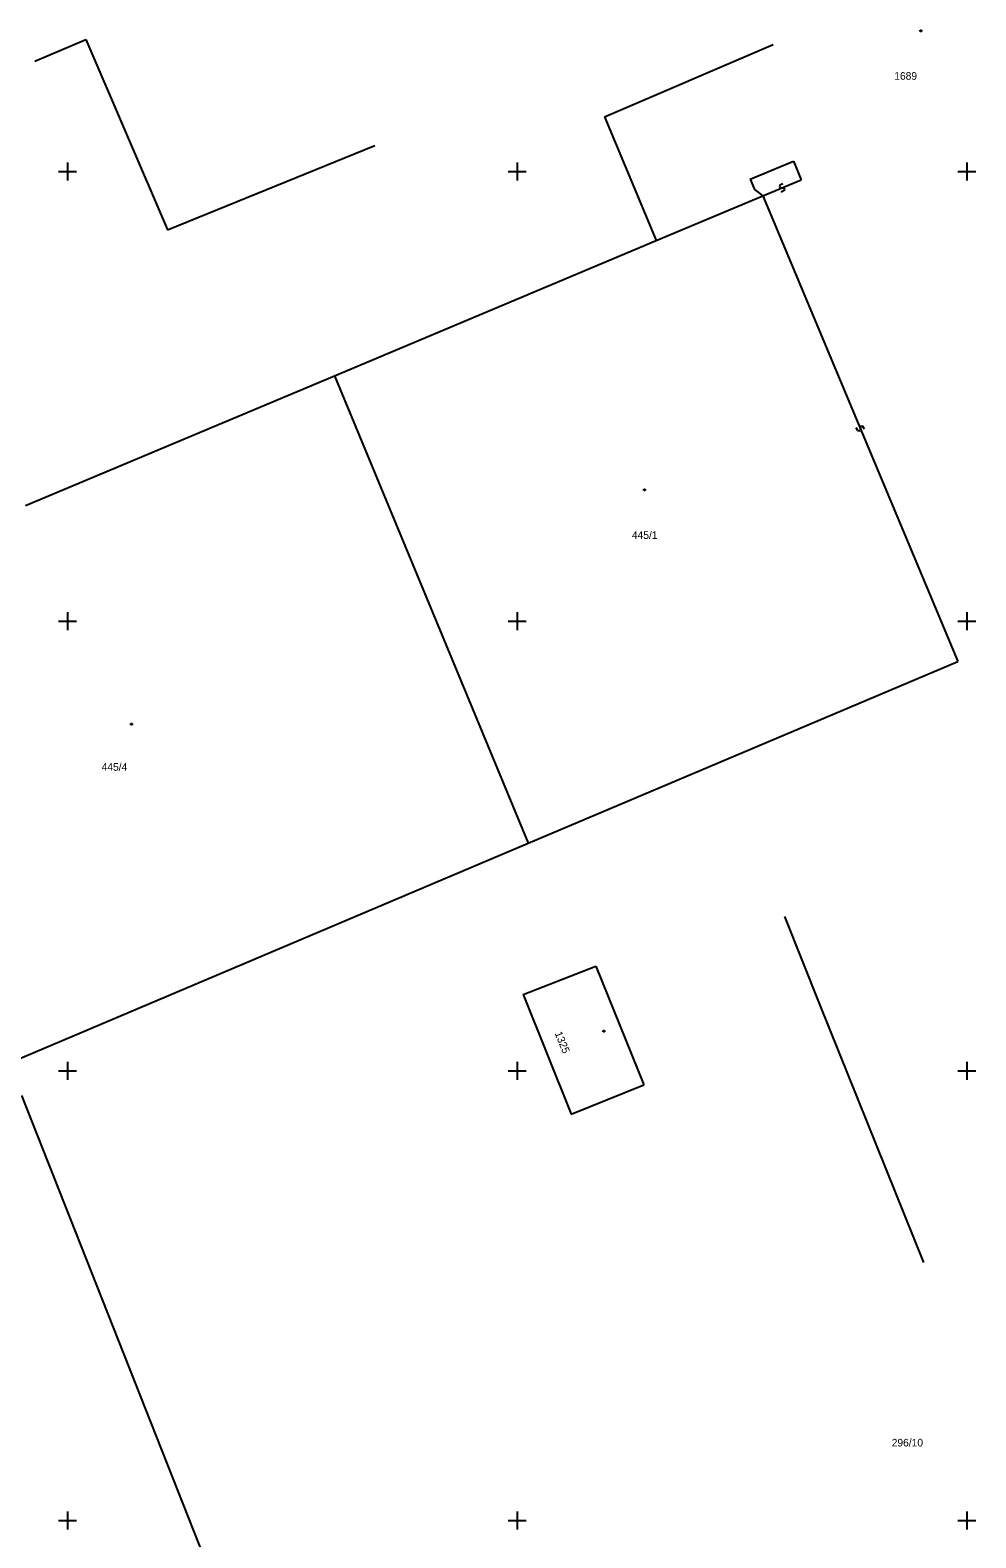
# Model space of a CAD drawing. Extents: x -492379 to -491966, y -1126153 to -1125860.
# Drawn here: x -492032.5 to -491969.4, y -1125961.2 to -1125860.6 of the extents above; entities that cross this region are included whole.
import ezdxf

# ---------------------------------------------------------------- set-up
doc = ezdxf.new("R2010")
doc.units = 0
doc.layers.add('katastrální mapa', color=7, linetype='Continuous')
doc.layers.add('síť', color=7, linetype='Continuous')

msp = doc.modelspace()

# ---------------------------------------------------------------- linework, layer by layer
at = {"layer": 'katastrální mapa'}
for p, q in [((-491973.11, -1125860.58), (-491973.02, -1125860.58)), ((-491973.11, -1125860.67), (-491973.11, -1125860.58)), ((-491973.02, -1125860.67), (-491973.11, -1125860.67)), ((-491973.02, -1125860.58), (-491973.02, -1125860.67)), ((-492032.17, -1125862.65), (-492028.77, -1125861.2)), ((-492028.77, -1125861.2), (-492023.33, -1125873.91)), ((-491994.18, -1125866.37), (-491982.91, -1125861.53)), ((-491994.18, -1125866.37), (-491990.72, -1125874.62)), ((-492023.33, -1125873.91), (-492009.49, -1125868.27)), ((-491984.45, -1125870.52), (-491981.57, -1125869.31)), ((-491981.57, -1125869.31), (-491981.05, -1125870.57)), ((-491984.45, -1125870.52), (-491984.17, -1125871.2)), ((-491983.61, -1125871.64), (-491981.05, -1125870.57)), ((-491982.47, -1125870.93), (-491982.5, -1125871.01)), ((-491982.5, -1125871.01), (-491982.48, -1125871.07)), ((-491982.28, -1125870.83), (-491982.47, -1125870.93)), ((-491990.72, -1125874.62), (-491983.61, -1125871.64)), ((-491984.17, -1125871.2), (-491983.61, -1125871.64)), ((-491983.61, -1125871.64), (-491970.6, -1125902.69)), ((-491982.48, -1125871.07), (-491982.4, -1125871.1)), ((-491982.4, -1125871.1), (-491982.26, -1125871.11)), ((-491982.19, -1125871.28), (-491982.38, -1125871.38)), ((-491982.26, -1125871.11), (-491982.18, -1125871.14)), ((-491982.16, -1125871.2), (-491982.19, -1125871.28)), ((-491982.18, -1125871.14), (-491982.16, -1125871.2)), ((-492012.18, -1125883.64), (-491990.72, -1125874.62)), ((-492032.79, -1125892.29), (-492012.18, -1125883.64)), ((-492012.18, -1125883.64), (-491999.27, -1125914.83)), ((-491977.28, -1125887.3), (-491977.38, -1125887.12)), ((-491977.1, -1125887.1), (-491977.11, -1125887.23)), ((-491977.07, -1125887.02), (-491977.1, -1125887.1)), ((-491977.01, -1125887), (-491977.07, -1125887.02)), ((-491976.93, -1125887.03), (-491977.01, -1125887)), ((-491976.83, -1125887.21), (-491976.93, -1125887.03)), ((-491977.2, -1125887.33), (-491977.28, -1125887.3)), ((-491977.14, -1125887.31), (-491977.2, -1125887.33)), ((-491977.11, -1125887.23), (-491977.14, -1125887.31)), ((-491991.55, -1125891.21), (-491991.46, -1125891.21)), ((-491991.55, -1125891.3), (-491991.55, -1125891.21)), ((-491991.46, -1125891.3), (-491991.55, -1125891.3)), ((-491991.46, -1125891.21), (-491991.46, -1125891.3)), ((-491999.27, -1125914.83), (-491970.6, -1125902.69)), ((-492025.77, -1125906.83), (-492025.68, -1125906.83)), ((-492025.77, -1125906.92), (-492025.77, -1125906.83)), ((-492025.68, -1125906.92), (-492025.77, -1125906.92)), ((-492025.68, -1125906.83), (-492025.68, -1125906.92)), ((-492043.92, -1125933.74), (-491999.27, -1125914.83)), ((-491982.17, -1125919.71), (-491979.8, -1125925.62)), ((-491999.6, -1125924.91), (-491994.74, -1125923.02)), ((-491994.74, -1125923.02), (-491991.55, -1125930.95)), ((-491999.6, -1125924.91), (-491996.4, -1125932.89)), ((-491979.8, -1125925.62), (-491972.9, -1125942.79)), ((-491994.25, -1125927.32), (-491994.16, -1125927.32)), ((-491994.25, -1125927.41), (-491994.25, -1125927.32)), ((-491994.16, -1125927.32), (-491994.16, -1125927.41)), ((-491994.16, -1125927.41), (-491994.25, -1125927.41)), ((-491996.4, -1125932.89), (-491991.55, -1125930.95)), ((-492033.05, -1125931.66), (-492007.69, -1125995.9))]:
    msp.add_line(p, q, dxfattribs=at)
at = {"layer": 'síť'}
for p, q in [((-492030.6, -1125870), (-492029.4, -1125870)), ((-492030, -1125869.4), (-492030, -1125870.6)), ((-492000.6, -1125870), (-491999.4, -1125870)), ((-492000, -1125869.4), (-492000, -1125870.6)), ((-491970.6, -1125870), (-491969.4, -1125870)), ((-491970, -1125869.4), (-491970, -1125870.6)), ((-492030.6, -1125900), (-492029.4, -1125900)), ((-492030, -1125899.4), (-492030, -1125900.6)), ((-492000.6, -1125900), (-491999.4, -1125900)), ((-492000, -1125899.4), (-492000, -1125900.6)), ((-491970.6, -1125900), (-491969.4, -1125900)), ((-491970, -1125899.4), (-491970, -1125900.6)), ((-492030.6, -1125930), (-492029.4, -1125930)), ((-492030, -1125929.4), (-492030, -1125930.6)), ((-492000.6, -1125930), (-491999.4, -1125930)), ((-492000, -1125929.4), (-492000, -1125930.6)), ((-491970.6, -1125930), (-491969.4, -1125930)), ((-491970, -1125929.4), (-491970, -1125930.6)), ((-492030, -1125959.4), (-492030, -1125960.6)), ((-492000, -1125959.4), (-492000, -1125960.6)), ((-491970, -1125959.4), (-491970, -1125960.6)), ((-492030.6, -1125960), (-492029.4, -1125960)), ((-492000.6, -1125960), (-491999.4, -1125960)), ((-491970.6, -1125960), (-491969.4, -1125960))]:
    msp.add_line(p, q, dxfattribs=at)

# ---------------------------------------------------------------- texts
at = {"layer": 'katastrální mapa'}
for s, p in [('1689', (-491974.84, -1125863.89)), ('445/1', (-491992.34, -1125894.52)), ('445/4', (-492027.71, -1125909.99)), ('296/10', (-491975.01, -1125955.07))]:
    msp.add_text(s, height=0.51, dxfattribs=at).set_placement(p)
msp.add_text('1325', height=0.51, rotation=292.041, dxfattribs=at).set_placement((-491997.5, -1125927.5))

doc.saveas('drawing.dxf')
